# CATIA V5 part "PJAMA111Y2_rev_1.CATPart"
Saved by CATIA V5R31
Part number: JAMA111Y2
Revision: 1
Nomenclature: BRACE_F_LH
Source: Unknown
Property "部品番号(A社)": "JAMA111Y2"
Property "部品名称(A社)": "BRACE_F_LH"
Property "Version(A社)": "1"
Property "材質(A社)": "SPHN2"
Property "板厚": "2.3"
Bounding box of the stored display mesh (mm): x 4110.044 to 4301.836, y -583.063 to -295, z 620.807 to 889.726
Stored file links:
  \\solize.local\damia\dept\DDE_Design\10_order\2305701_JAMA_変換検証STEP3_お手本モデル作成\work\02_マツダ_板金\10_CATIA_V5\231211\PJAMA111Y2_rev_1.CATPart
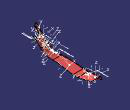
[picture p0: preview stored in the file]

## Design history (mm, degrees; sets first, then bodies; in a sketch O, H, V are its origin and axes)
TTRSSet1
f4a2d38f3ddc11d3a929006094b99c4b_11 "CATTPSSet"
Set1
  DatumSurface1 "OPEN_SHELL #621"
Set2 "DATUM"
  Circle1: stored without definition
  DatumCurve1
  Point1 to Point9: stored without definition
  DatumCurve2
  DatumCurve3
  AxisSystem1: origin (4276, -518.7, 860), X (-1, 0, 0), Y (0, 0, 1), Z (0, 1, 0)
  AxisSystem2: origin (4236.4075, -538, 829), X (0.4695, 0, 0.8829), Y (0, -1, 0), Z (0.8829, 0, -0.4695)
  AxisSystem3: origin (4214.426, -540, 787.659), X (-0.4695, 0, -0.8829), Y (0, -1, 0), Z (-0.8829, 0, 0.4695)
  AxisSystem4: origin (4205.0366, -540, 770), X (-0.4695, 0, -0.8829), Y (0, -1, 0), Z (-0.8829, 0, 0.4695)
  AxisSystem5: origin (4185.1699, -537.6067, 736.3058), X (0.4592, -0.2079, 0.8637), Y (-0.0976, -0.9781, -0.1836), Z (0.8829, 0, -0.4695)
  AxisSystem6: origin (4178.6124, -534.6377, 723.9728), X (0.4592, -0.2079, 0.8637), Y (-0.0976, -0.9781, -0.1836), Z (0.8829, 0, -0.4695)
  AxisSystem7: origin (4150, -468, 678), X (0.3596, 0.6428, 0.6764), Y (0.3018, -0.766, 0.5675), Z (0.8829, 0, -0.4695)
  AxisSystem8: origin (4165.1, -344.1, 701.7), X (0.4226, 0.9063, 0), Y (0.9063, -0.4226, 0), Z (0, 0, -1)
  AxisSystem9: origin (4161, -307, 701.7), X (-1, 0, 0), Y (0, -1, 0), Z (0, 0, 1)
  DatumCurve4
  AxisSystem10: origin (4247.2148, -526, 845), X (0, 1, 0), Y (1, 0, 0), Z (0, 0, -1)
  Sketch1 on XY plane of AxisSystem10, origin (4247.2148, -526, 845), H (0, -1, 0), V (1, 0, 0)
    point P1 (7.621, 31.7446)
    line L1 (7.621, 31.7446) -> (22.621, 31.7446)
    point P2 (22.621, 31.7446)
    line L2 (22.621, 31.7446) -> (17.621, 33.0844)
    construction line L3 (17.621, 33.0844) -> (17.621, 30.4049)
    line L4 (17.621, 30.4049) -> (22.621, 31.7446)
    distance L3 P1 = 10
    distance L3 P2 = 5
    angle L2 L4 = 30
    horizontal: L1 H
    vertical: L3 V
    symmetry: L2 L4 L1
Body1 (main body)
